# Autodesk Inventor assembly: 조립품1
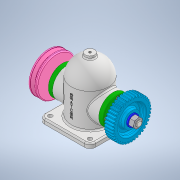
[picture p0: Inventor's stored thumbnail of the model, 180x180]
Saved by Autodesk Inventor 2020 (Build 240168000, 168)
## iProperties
Created: 2021-07
Part Number: 조립품1
Document SubType Name: Assembly
Designer: Owner
Author: Owner
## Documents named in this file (14)
- C:\Users\Owner\Desktop\710716V1008\조립품1.iam
- C:\Users\Owner\Desktop\710716V1008\본체.ipt
- C:\Users\Owner\Desktop\710716V1008\V-벨트풀리.ipt
- V-벨트풀리.ipt
- C:\Users\Owner\Desktop\710716V1008\너트 M12x1.25.ipt
- C:\Users\Owner\Desktop\710716V1008\베어링 6203.ipt
- C:\Users\Owner\Desktop\710716V1008\볼트 M4.ipt
- C:\Users\Owner\Desktop\710716V1008\부시.ipt
- C:\Users\Owner\Desktop\710716V1008\스퍼기어.ipt
- C:\Users\Owner\Desktop\710716V1008\오일 실 26 38 8.ipt
- C:\Users\Owner\Desktop\710716V1008\와셔 12x24.ipt
- C:\Users\Owner\Desktop\710716V1008\축.ipt
- C:\Users\Owner\Desktop\710716V1008\커버.ipt
- C:\Users\Owner\Desktop\710716V1008\키 5x5x12.ipt
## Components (1 placed, 1 different names)
1. V-벨트풀리:1
